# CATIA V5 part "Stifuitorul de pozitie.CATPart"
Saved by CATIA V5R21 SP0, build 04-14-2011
Part number: Part1.6
Bounding box of the stored display mesh (mm): x -2.5 to 2.5, y -2.5 to 2.5, z 0 to 20
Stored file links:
  C:\Users\MIRCEA\Desktop\MOM\Mogan\model\Stifuitorul de pozitie.CATPart
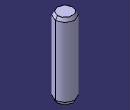
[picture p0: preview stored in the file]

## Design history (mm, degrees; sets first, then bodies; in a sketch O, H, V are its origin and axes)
Body1 (main body)
  Sketch1 on xy-plane, origin (0, 0, 0), H (1, 0, 0), V (0, 1, 0)
    circle A1 centre (0, 0) radius 2.5
    radius A1 = 2.5
  Pad1: profile Sketch1, direction (0, 0, 1), length 20
  Chamfer1: length 0.5, angle 60, on end face of Pad1; edge [start face of Pad1 | face of Pad1 from Sketch1.A1]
